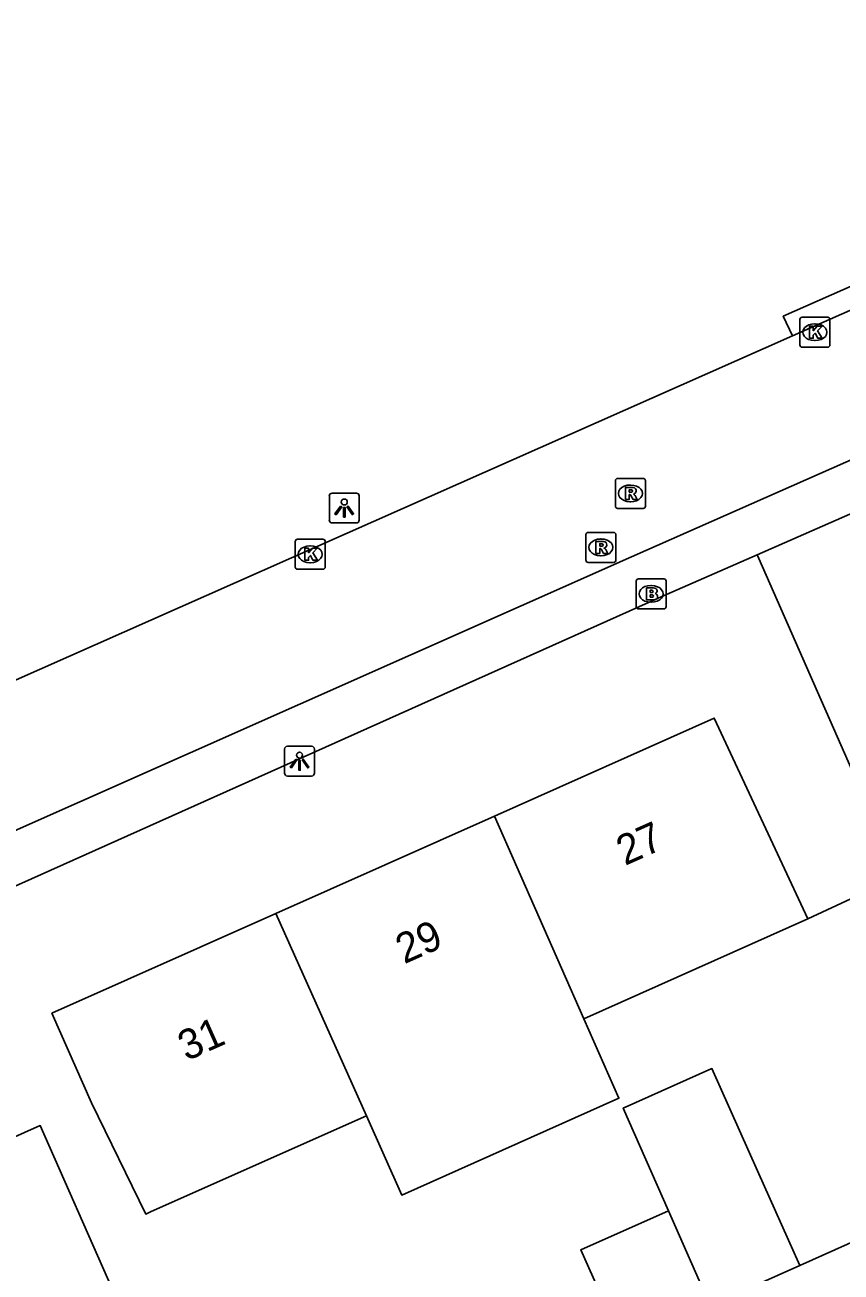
# Model space of a CAD drawing. Extents: x 156664 to 157568, y 383571 to 384421.
# Drawn here: x 157175 to 157202.25, y 383830.19 to 383871.83 of the extents above; entities that cross this region are included whole.
import ezdxf

# ---------------------------------------------------------------- set-up
doc = ezdxf.new("R2010")
doc.units = 0
for name, color, linetype in [('IMGEO_Brandkraan', 7, 'Continuous'), ('IMGEO_Groenvoorziening', 7, 'Continuous'), ('IMGEO_Hek', 7, 'Continuous'), ('IMGEO_Kolk', 7, 'Continuous'), ('IMGEO_Lichtpunt', 7, 'Continuous'), ('IMGEO_Pand', 7, 'Continuous'), ('IMGEO_Pand_nummerreeks', 7, 'Continuous'), ('IMGEO_Rijbaan_lokaal_open', 7, 'Continuous'), ('IMGEO_Rioolput', 7, 'Continuous'), ('IMGEO_Voetpad_halfverhard', 7, 'Continuous'), ('IMGEO_Voetpad_open', 7, 'Continuous')]:
    doc.layers.add(name, color=color, linetype=linetype)

msp = doc.modelspace()

# ---------------------------------------------------------------- linework, layer by layer
at = {"layer": 'IMGEO_Brandkraan'}
for p, q in [((157195.411, 383852.406), (157195.411, 383853.258)), ((157195.486, 383853.332), (157196.338, 383853.332)), ((157196.412, 383853.258), (157196.412, 383852.406)), ((157195.899, 383853.112), (157195.924, 383853.112)), ((157195.922, 383852.552), (157195.897, 383852.552)), ((157196.338, 383852.332), (157195.486, 383852.332))]:
    msp.add_line(p, q, dxfattribs=at)
for points in [[(157195.411, 383852.406), (157195.411, 383853.258)], [(157195.486, 383853.332), (157196.338, 383853.332)], [(157196.412, 383853.258), (157196.412, 383852.406)], [(157195.759, 383853.032), (157195.759, 383852.632), (157195.972, 383852.632)], [(157195.99, 383853.032), (157195.759, 383853.032)], [(157195.938, 383852.951), (157195.884, 383852.951), (157195.884, 383852.875)], [(157195.884, 383852.875), (157195.937, 383852.875)], [(157195.946, 383852.799), (157195.884, 383852.799), (157195.884, 383852.718)], [(157195.884, 383852.718), (157195.946, 383852.718)], [(157196.338, 383852.332), (157195.486, 383852.332)]]:
    msp.add_lwpolyline(points, dxfattribs=at)
for centre, radius, start, end in [((157195.488, 383853.256), 0.0765, 91.552, 178.448), ((157195.488, 383853.256), 0.0765, 91.552, 178.448), ((157196.336, 383853.256), 0.0765, 1.552, 88.448), ((157196.336, 383853.256), 0.0765, 1.552, 88.448), ((157195.939, 383852.913), 0.0379, 267.8285, 90.9355), ((157195.947, 383852.758), 0.0404, 269.8759, 90.5077), ((157195.994, 383852.887), 0.145, 59.4692, 91.5367), ((157196.019, 383852.934), 0.0922, 285.5137, 58.1501), ((157196.024, 383852.742), 0.105, 301.3115, 78.989), ((157195.488, 383852.408), 0.0765, 181.552, 268.448), ((157195.488, 383852.408), 0.0765, 181.552, 268.448), ((157195.978, 383852.883), 0.251, 268.6676, 293.5347), ((157196.336, 383852.408), 0.0765, 271.552, 358.448), ((157196.336, 383852.408), 0.0765, 271.552, 358.448)]:
    msp.add_arc(centre, radius, start, end, dxfattribs=at)
for centre, major_axis, ratio, start_param, end_param in [((157195.898, 383852.832), (-0.387, 0.002), 0.722429, 4.712389, 7.853982), ((157195.923, 383852.832), (-0.39, 0.002), 0.717154, 1.570796, 4.712389)]:
    msp.add_ellipse(centre, major_axis=major_axis, ratio=ratio, start_param=start_param, end_param=end_param, dxfattribs=at)
at = {"layer": 'IMGEO_Groenvoorziening'}
msp.add_lwpolyline([(157199.451, 383854.14), (157199.506, 383854.014), (157208.411, 383833.785), (157200.875, 383830.41)], dxfattribs=at)
at = {"layer": 'IMGEO_Hek'}
msp.add_lwpolyline([(157201.148, 383841.98), (157204.179, 383843.399), (157208.411, 383833.785), (157200.875, 383830.41)], dxfattribs=at)
at = {"layer": 'IMGEO_Kolk'}
for p, q in [((157200.879, 383861.143), (157200.879, 383861.995)), ((157200.954, 383862.069), (157201.806, 383862.069)), ((157201.88, 383861.995), (157201.88, 383861.143)), ((157201.367, 383861.849), (157201.392, 383861.849)), ((157201.39, 383861.289), (157201.365, 383861.289)), ((157201.806, 383861.069), (157200.954, 383861.069)), ((157184.027, 383853.728), (157184.027, 383854.58)), ((157184.102, 383854.654), (157184.954, 383854.654)), ((157184.515, 383854.434), (157184.54, 383854.434)), ((157185.028, 383854.58), (157185.028, 383853.728)), ((157184.954, 383853.654), (157184.102, 383853.654)), ((157184.538, 383853.874), (157184.513, 383853.874))]:
    msp.add_line(p, q, dxfattribs=at)
for points in [[(157200.879, 383861.143), (157200.879, 383861.995)], [(157200.954, 383862.069), (157201.806, 383862.069)], [(157201.88, 383861.995), (157201.88, 383861.143)], [(157201.2, 383861.769), (157201.323, 383861.769), (157201.323, 383861.618), (157201.453, 383861.769), (157201.617, 383861.769), (157201.471, 383861.618), (157201.624, 383861.369), (157201.472, 383861.369), (157201.387, 383861.533), (157201.323, 383861.466), (157201.323, 383861.369), (157201.2, 383861.369), (157201.2, 383861.769)], [(157201.806, 383861.069), (157200.954, 383861.069)], [(157184.027, 383853.728), (157184.027, 383854.58)], [(157184.102, 383854.654), (157184.954, 383854.654)], [(157185.028, 383854.58), (157185.028, 383853.728)], [(157184.348, 383854.354), (157184.471, 383854.354), (157184.471, 383854.203), (157184.601, 383854.354), (157184.765, 383854.354), (157184.619, 383854.203), (157184.772, 383853.954), (157184.62, 383853.954), (157184.535, 383854.118), (157184.471, 383854.051), (157184.471, 383853.954), (157184.348, 383853.954), (157184.348, 383854.354)], [(157184.954, 383853.654), (157184.102, 383853.654)]]:
    msp.add_lwpolyline(points, dxfattribs=at)
for centre, start, end in [((157200.956, 383861.993), 91.552, 178.448), ((157200.956, 383861.993), 91.552, 178.448), ((157201.804, 383861.993), 1.552, 88.448), ((157201.804, 383861.993), 1.552, 88.448), ((157200.956, 383861.145), 181.552, 268.448), ((157200.956, 383861.145), 181.552, 268.448), ((157201.804, 383861.145), 271.552, 358.448), ((157201.804, 383861.145), 271.552, 358.448), ((157184.104, 383854.578), 91.552, 178.448), ((157184.104, 383854.578), 91.552, 178.448), ((157184.952, 383854.578), 1.552, 88.448), ((157184.952, 383854.578), 1.552, 88.448), ((157184.104, 383853.73), 181.552, 268.448), ((157184.104, 383853.73), 181.552, 268.448), ((157184.952, 383853.73), 271.552, 358.448), ((157184.952, 383853.73), 271.552, 358.448)]:
    msp.add_arc(centre, 0.0765, start, end, dxfattribs=at)
for centre, major_axis, ratio, start_param, end_param in [((157201.366, 383861.569), (-0.387, 0.002), 0.722429, 4.712389, 7.853982), ((157201.391, 383861.569), (-0.39, 0.002), 0.717154, 1.570796, 4.712389), ((157184.514, 383854.154), (-0.387, 0.002), 0.722429, 4.712389, 7.853982), ((157184.539, 383854.154), (-0.39, 0.002), 0.717154, 1.570796, 4.712389)]:
    msp.add_ellipse(centre, major_axis=major_axis, ratio=ratio, start_param=start_param, end_param=end_param, dxfattribs=at)
at = {"layer": 'IMGEO_Lichtpunt'}
for p, q in [((157185.166, 383856.102), (157185.166, 383855.295)), ((157185.166, 383856.102), (157185.166, 383855.295)), ((157186.068, 383856.197), (157185.26, 383856.197)), ((157186.068, 383856.197), (157185.26, 383856.197)), ((157186.162, 383855.295), (157186.162, 383856.102)), ((157186.162, 383855.295), (157186.162, 383856.102)), ((157185.26, 383855.201), (157186.068, 383855.201)), ((157185.26, 383855.201), (157186.068, 383855.201)), ((157183.672, 383847.651), (157183.672, 383846.844)), ((157183.672, 383847.651), (157183.672, 383846.844)), ((157184.574, 383847.746), (157183.766, 383847.746)), ((157184.574, 383847.746), (157183.766, 383847.746)), ((157184.668, 383846.844), (157184.668, 383847.651)), ((157184.668, 383846.844), (157184.668, 383847.651)), ((157183.766, 383846.75), (157184.574, 383846.75)), ((157183.766, 383846.75), (157184.574, 383846.75))]:
    msp.add_line(p, q, dxfattribs=at)
for points in [[(157185.54, 383855.766), (157185.579, 383855.738), (157185.391, 383855.476), (157185.353, 383855.503), (157185.54, 383855.766)], [(157185.642, 383855.718), (157185.689, 383855.718), (157185.689, 383855.396), (157185.642, 383855.396), (157185.642, 383855.718)], [(157185.752, 383855.738), (157185.79, 383855.765), (157185.977, 383855.503), (157185.938, 383855.475), (157185.752, 383855.738)], [(157184.046, 383847.315), (157184.085, 383847.287), (157183.897, 383847.025), (157183.859, 383847.052), (157184.046, 383847.315)], [(157184.148, 383847.267), (157184.195, 383847.267), (157184.195, 383846.945), (157184.148, 383846.945), (157184.148, 383847.267)], [(157184.258, 383847.287), (157184.296, 383847.314), (157184.483, 383847.052), (157184.444, 383847.024), (157184.258, 383847.287)]]:
    msp.add_lwpolyline(points, dxfattribs=at)
for centre in [(157185.665, 383855.9), (157184.171, 383847.449)]:
    msp.add_circle(centre, 0.0994, dxfattribs=at)
for centre, start, end in [((157185.26, 383856.102), 90, 180), ((157185.26, 383856.102), 90, 180), ((157186.068, 383856.102), 0, 90), ((157186.068, 383856.102), 0, 90), ((157185.26, 383855.295), 180, 270), ((157185.26, 383855.295), 180, 270), ((157186.068, 383855.295), 270, 0), ((157186.068, 383855.295), 270, 360), ((157183.766, 383847.651), 90, 180), ((157183.766, 383847.651), 90, 180), ((157184.574, 383847.651), 0, 90), ((157184.574, 383847.651), 0, 90), ((157183.766, 383846.844), 180, 270), ((157183.766, 383846.844), 180, 270), ((157184.574, 383846.844), 270, 0), ((157184.574, 383846.844), 270, 360)]:
    msp.add_arc(centre, 0.0946, start, end, dxfattribs=at)
at = {"layer": 'IMGEO_Pand'}
for points in [[(157193.665, 383838.645), (157201.148, 383841.98), (157198.02, 383848.688), (157190.679, 383845.415)], [(157190.679, 383845.415), (157183.381, 383842.162)], [(157193.665, 383838.645), (157190.679, 383845.415)], [(157183.381, 383842.162), (157175.902, 383838.828), (157177.225, 383835.84), (157179.038, 383832.126), (157179.218, 383832.206), (157186.402, 383835.408)], [(157186.402, 383835.408), (157183.381, 383842.162)], [(157186.402, 383835.408), (157187.586, 383832.761), (157194.835, 383835.992), (157193.665, 383838.645)], [(157200.875, 383830.41), (157199.468, 383833.565), (157197.943, 383836.985), (157194.98, 383835.665), (157196.491, 383832.238)], [(157166.087, 383818.909), (157170.847, 383820.534), (157173.099, 383821.272), (157172.919, 383821.821), (157172.08, 383824.782), (157170.169, 383830.692), (157172.557, 383831.756), (157174.246, 383827.965), (157177.927, 383829.605), (157175.515, 383835.08), (157170.373, 383832.791), (157169.459, 383832.385), (157169.407, 383832.596), (157162.399, 383830.305)], [(157196.491, 383832.238), (157193.563, 383830.933), (157194.969, 383827.778), (157197.76, 383829.022)], [(157196.491, 383832.238), (157197.885, 383829.077)], [(157197.885, 383829.077), (157200.875, 383830.41)]]:
    msp.add_lwpolyline(points, dxfattribs=at)
at = {"layer": 'IMGEO_Rijbaan_lokaal_open'}
for points in [[(157222.581, 383871.155), (157200.633, 383861.445)], [(157200.633, 383861.445), (157164.329, 383845.363), (157154.951, 383841.199), (157154.389, 383841.05), (157153.812, 383840.967)], [(157209.005, 383860.154), (157203.743, 383857.815), (157195.261, 383854.066), (157165.775, 383840.978)]]:
    msp.add_lwpolyline(points, dxfattribs=at)
at = {"layer": 'IMGEO_Rioolput'}
for p, q in [((157194.718, 383855.761), (157194.718, 383856.613)), ((157194.793, 383856.687), (157195.645, 383856.687)), ((157195.719, 383856.613), (157195.719, 383855.761)), ((157195.206, 383856.467), (157195.231, 383856.467)), ((157195.645, 383855.687), (157194.793, 383855.687)), ((157195.229, 383855.907), (157195.204, 383855.907)), ((157193.808, 383854.885), (157194.66, 383854.885)), ((157193.733, 383853.959), (157193.733, 383854.811)), ((157194.221, 383854.665), (157194.246, 383854.665)), ((157194.734, 383854.811), (157194.734, 383853.959)), ((157194.244, 383854.105), (157194.219, 383854.105)), ((157194.66, 383853.885), (157193.808, 383853.885))]:
    msp.add_line(p, q, dxfattribs=at)
for points in [[(157194.718, 383855.761), (157194.718, 383856.613)], [(157194.793, 383856.687), (157195.645, 383856.687)], [(157195.719, 383856.613), (157195.719, 383855.761)], [(157195.307, 383856.385), (157195.055, 383856.387), (157195.055, 383855.987)], [(157195.055, 383855.987), (157195.179, 383855.987), (157195.179, 383856.149), (157195.19, 383856.149)], [(157195.233, 383856.306), (157195.179, 383856.306), (157195.179, 383856.225)], [(157195.179, 383856.225), (157195.231, 383856.225)], [(157195.237, 383856.12), (157195.308, 383855.987), (157195.448, 383855.987), (157195.383, 383856.113)], [(157195.645, 383855.687), (157194.793, 383855.687)], [(157193.808, 383854.885), (157194.66, 383854.885)], [(157193.733, 383853.959), (157193.733, 383854.811)], [(157194.322, 383854.583), (157194.07, 383854.585), (157194.07, 383854.185)], [(157194.248, 383854.504), (157194.194, 383854.504), (157194.194, 383854.423)], [(157194.194, 383854.423), (157194.246, 383854.423)], [(157194.734, 383854.811), (157194.734, 383853.959)], [(157194.07, 383854.185), (157194.194, 383854.185), (157194.194, 383854.347), (157194.205, 383854.347)], [(157194.252, 383854.318), (157194.323, 383854.185), (157194.463, 383854.185), (157194.398, 383854.311)], [(157194.66, 383853.885), (157193.808, 383853.885)]]:
    msp.add_lwpolyline(points, dxfattribs=at)
for centre, radius, start, end in [((157194.795, 383856.611), 0.0765, 91.552, 178.448), ((157194.795, 383856.611), 0.0765, 91.552, 178.448), ((157195.643, 383856.611), 0.0765, 1.552, 88.448), ((157195.643, 383856.611), 0.0765, 1.552, 88.448), ((157195.189, 383856.096), 0.0533, 26.0293, 88.6989), ((157195.215, 383856.414), 0.19, 274.7715, 282.9687), ((157195.239, 383856.21), 0.0964, 77.0061, 93.1865), ((157195.253, 383856.267), 0.0378, 276.6634, 79.6772), ((157195.306, 383856.275), 0.109, 350.3612, 89.416), ((157195.304, 383856.275), 0.112, 277.5842, 350.9817), ((157195.288, 383856.06), 0.108, 29.5134, 73.7905), ((157194.795, 383855.763), 0.0765, 181.552, 268.448), ((157194.795, 383855.763), 0.0765, 181.552, 268.448), ((157195.643, 383855.763), 0.0765, 271.552, 358.448), ((157195.643, 383855.763), 0.0765, 271.552, 358.448), ((157193.81, 383854.809), 0.0765, 91.552, 178.448), ((157193.81, 383854.809), 0.0765, 91.552, 178.448), ((157194.658, 383854.809), 0.0765, 1.552, 88.448), ((157194.658, 383854.809), 0.0765, 1.552, 88.448), ((157194.23, 383854.612), 0.19, 274.7715, 282.9687), ((157194.254, 383854.408), 0.0964, 77.0061, 93.1865), ((157194.268, 383854.465), 0.0378, 276.6634, 79.6772), ((157194.321, 383854.473), 0.109, 350.3612, 89.416), ((157194.319, 383854.473), 0.112, 277.5842, 350.9817), ((157194.204, 383854.294), 0.0533, 26.0293, 88.6989), ((157194.303, 383854.258), 0.108, 29.5134, 73.7905), ((157193.81, 383853.961), 0.0765, 181.552, 268.448), ((157193.81, 383853.961), 0.0765, 181.552, 268.448), ((157194.658, 383853.961), 0.0765, 271.552, 358.448), ((157194.658, 383853.961), 0.0765, 271.552, 358.448)]:
    msp.add_arc(centre, radius, start, end, dxfattribs=at)
for centre, major_axis, ratio, start_param, end_param in [((157195.205, 383856.187), (-0.387, 0.002), 0.722429, 4.712389, 7.853982), ((157195.23, 383856.187), (-0.39, 0.002), 0.717154, 1.570796, 4.712389), ((157194.22, 383854.385), (-0.387, 0.002), 0.722429, 4.712389, 7.853982), ((157194.245, 383854.385), (-0.39, 0.002), 0.717154, 1.570796, 4.712389)]:
    msp.add_ellipse(centre, major_axis=major_axis, ratio=ratio, start_param=start_param, end_param=end_param, dxfattribs=at)
at = {"layer": 'IMGEO_Voetpad_halfverhard'}
msp.add_lwpolyline([(157222.581, 383871.155), (157222.293, 383871.829), (157207.433, 383865.249), (157200.322, 383862.1), (157200.633, 383861.445)], dxfattribs=at)
at = {"layer": 'IMGEO_Voetpad_open'}
for points in [[(157199.451, 383854.14), (157205.01, 383856.572)], [(157166.456, 383839.4), (157196.244, 383852.736), (157199.451, 383854.14)]]:
    msp.add_lwpolyline(points, dxfattribs=at)

# ---------------------------------------------------------------- texts
at = {"layer": 'IMGEO_Pand_nummerreeks'}
for s, p in [('27', (157195.038, 383843.746)), ('29', (157187.667, 383840.461)), ('31', (157180.399, 383837.222))]:
    msp.add_text(s, height=1, rotation=24.0184, dxfattribs=at).set_placement(p)

doc.saveas('drawing.dxf')
